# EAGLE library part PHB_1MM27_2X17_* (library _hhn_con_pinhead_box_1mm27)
Pin Header Box-Type, 1.27mm/0.5"/50mil Pitch, 2x17 Circuits Note: see library description for an important note about THT-version
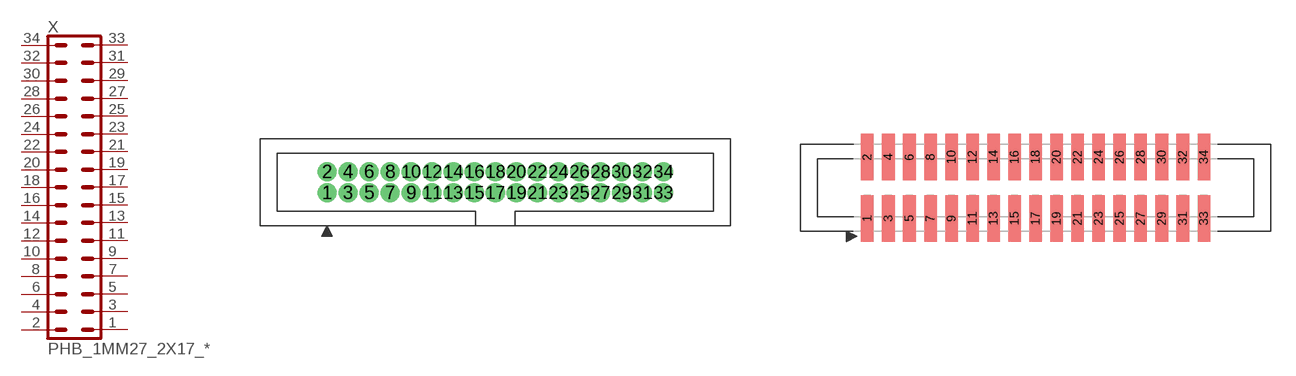
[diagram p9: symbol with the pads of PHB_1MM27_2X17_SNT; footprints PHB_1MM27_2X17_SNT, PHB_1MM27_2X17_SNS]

Designator prefix X

## PHB_1MM27_2X17_SNT  [PHB_1MM27_2X17_SNT]
1  1  pas
2  2  pas
3  3  pas
4  4  pas
5  5  pas
6  6  pas
7  7  pas
8  8  pas
9  9  pas
10  10  pas
11  11  pas
12  12  pas
13  13  pas
14  14  pas
15  15  pas
16  16  pas
17  17  pas
18  18  pas
19  19  pas
20  20  pas
21  21  pas
22  22  pas
23  23  pas
24  24  pas
25  25  pas
26  26  pas
27  27  pas
28  28  pas
29  29  pas
30  30  pas
31  31  pas
32  32  pas
33  33  pas
34  34  pas

## PHB_1MM27_2X17_SNS  [PHB_1MM27_2X17_SNS]
Pads as for PHB_1MM27_2X17_SNT

## Footprint PHB_1MM27_2X17_SNT (pad centres in mm)
Pin Header Box-Type, 1.27mm Pitch, 2x17 circuits, Straight, No Locking, THT Important Note: Diameter in this lbr is set to a specific value (NOT 'auto' = 0), this is ignored by actual eagle versions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
drill 0.65 pad 1 round: 1 -10.16,-0.635; 2 -10.16,0.635; 3 -8.89,-0.635; 4 -8.89,0.635; 5 -7.62,-0.635; 6 -7.62,0.635; 7 -6.35,-0.635; 8 -6.35,0.635; 9 -5.08,-0.635; 10 -5.08,0.635; 11 -3.81,-0.635; 12 -3.81,0.635; 13 -2.54,-0.635; 14 -2.54,0.635; 15 -1.27,-0.635; 16 -1.27,0.635; 17 0,-0.635; 18 0,0.635; 19 1.27,-0.635; 20 1.27,0.635; 21 2.54,-0.635; 22 2.54,0.635; 23 3.81,-0.635; 24 3.81,0.635; 25 5.08,-0.635; 26 5.08,0.635; 27 6.35,-0.635; 28 6.35,0.635; 29 7.62,-0.635; 30 7.62,0.635; 31 8.89,-0.635; 32 8.89,0.635; 33 10.16,-0.635; 34 10.16,0.635

## Footprint PHB_1MM27_2X17_SNS (pad centres in mm)
Pin Header Box-Type, 1.27mm Pitch, 2x17 circuits, Straight, No Locking, SMT
smd 0.76 x 2.8: 1 -10.16,-1.85; 2 -10.16,1.85; 3 -8.89,-1.85; 4 -8.89,1.85; 5 -7.62,-1.85; 6 -7.62,1.85; 7 -6.35,-1.85; 8 -6.35,1.85; 9 -5.08,-1.85; 10 -5.08,1.85; 11 -3.81,-1.85; 12 -3.81,1.85; 13 -2.54,-1.85; 14 -2.54,1.85; 15 -1.27,-1.85; 16 -1.27,1.85; 17 0,-1.85; 18 0,1.85; 19 1.27,-1.85; 20 1.27,1.85; 21 2.54,-1.85; 22 2.54,1.85; 23 3.81,-1.85; 24 3.81,1.85; 25 5.08,-1.85; 26 5.08,1.85; 27 6.35,-1.85; 28 6.35,1.85; 29 7.62,-1.85; 30 7.62,1.85; 31 8.89,-1.85; 32 8.89,1.85; 33 10.16,-1.85; 34 10.16,1.85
